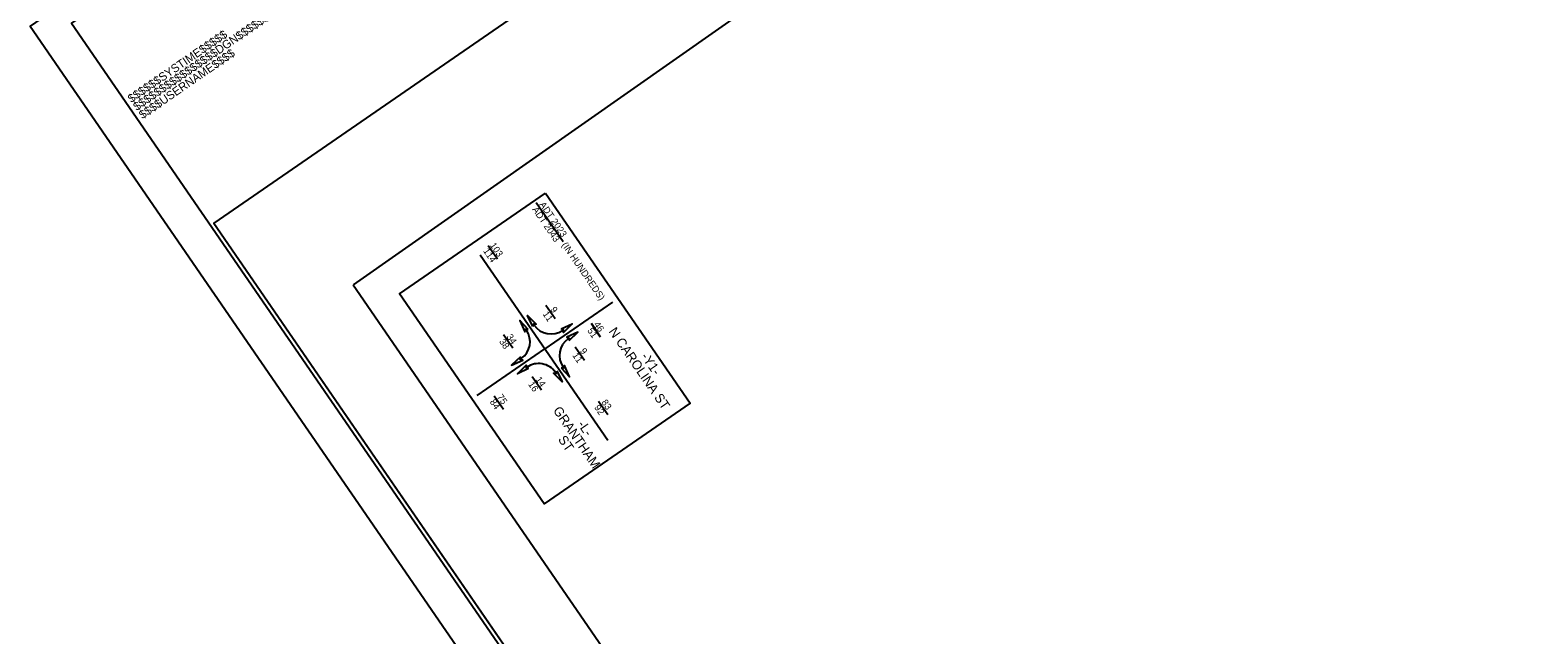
# Model space of a CAD drawing. Extents: x 2297526 to 2298642, y 599613 to 600819.
# Drawn here: x 2297526 to 2298094, y 600216 to 600444 of the extents above; entities that cross this region are included whole.
import ezdxf

# ---------------------------------------------------------------- set-up
doc = ezdxf.new("R2010")
doc.units = 0
for name, color, linetype in [('Default', 7, 'Continuous'), ('Exist DTM Drainline Cogo Comment', 7, 'Continuous'), ('Exist DTM Drainline Cogo Elevation', 7, 'Continuous'), ('Exist Property Iron Pin Cogo Number', 7, 'Continuous'), ('Exist Roads Curbs Cogo Number', 7, 'Continuous'), ('Exist Roads Curbs Cogo Point CELL', 7, 'Continuous'), ('Exist Roads EOP Cogo Elevation', 7, 'Continuous')]:
    doc.layers.add(name, color=color, linetype=linetype)

msp = doc.modelspace()

# ---------------------------------------------------------------- linework, layer by layer
at = {"layer": 'Default'}
for points in [[(2297715.05, 600332.05), (2297713.1, 600336.18), (2297716.33, 600332.93), (2297715.33, 600332.94)], [(2297713.36, 600330.96), (2297710.19, 600334.26), (2297712.07, 600330.08), (2297712.42, 600331.02)], [(2297725.74, 600331.14), (2297729.87, 600333.09), (2297726.63, 600329.86), (2297726.63, 600330.86)], [(2297728.74, 600326.79), (2297732.03, 600329.95), (2297727.86, 600328.07), (2297728.79, 600327.72)], [(2297710.39, 600320.65), (2297707.1, 600317.49), (2297711.28, 600319.37), (2297710.34, 600319.71)], [(2297713.43, 600316.24), (2297709.3, 600314.3), (2297712.54, 600317.53), (2297712.54, 600316.53)], [(2297724.12, 600315.33), (2297726.07, 600311.2), (2297722.84, 600314.45), (2297723.84, 600314.44)], [(2297725.78, 600316.47), (2297728.94, 600313.18), (2297727.06, 600317.36), (2297726.71, 600316.42)]]:
    msp.add_lwpolyline(points, close=True, dxfattribs=at)
for centre, start, end in [((2297706.34, 600326.3), 304.554, 34.554), ((2297721.91, 600336.94), 214.5541, 304.5541), ((2297732.8, 600321.14), 124.554, 214.554), ((2297717.26, 600310.44), 34.5541, 124.5541)]:
    msp.add_arc(centre, 7.69, start, end, dxfattribs=at)
at = {"layer": 'Exist DTM Drainline Cogo Comment'}
msp.add_lwpolyline([(2298629.8, 599981.76), (2298062.67, 600805.27), (2297541.29, 600446.21), (2298108.42, 599622.7)], close=True, dxfattribs=at)
at = {"layer": 'Exist DTM Drainline Cogo Elevation'}
msp.add_lwpolyline([(2298624.28, 599987.07), (2298113.82, 600728.3), (2297594.96, 600370.97), (2298105.42, 599629.74)], close=True, dxfattribs=at)
at = {"layer": 'Exist Property Iron Pin Cogo Number'}
msp.add_lwpolyline([(2297647.43, 600347.7), (2298036.32, 599783), (2298066.14, 599803.53), (2298144.6, 599689.59), (2298480.39, 599975.84), (2298444.85, 600027.45), (2298522.99, 600081.26), (2298287.23, 600423.6), (2298114.33, 600674.66)], close=True, dxfattribs=at)
at = {"layer": 'Exist Roads Curbs Cogo Number'}
msp.add_lwpolyline([(2298113.82, 600728.3), (2297594.98, 600370.97), (2298105.44, 599629.74), (2298525.54, 599919.07), (2298457.47, 600017.93), (2298556.21, 600085.92)], close=True, dxfattribs=at)
at = {"layer": 'Exist Roads Curbs Cogo Point CELL'}
msp.add_lwpolyline([(2298642.42, 599987.17), (2298069.34, 600819.33), (2297525.77, 600444.99), (2298098.85, 599612.83)], close=True, dxfattribs=at)
at = {"layer": 'Exist Roads EOP Cogo Elevation'}
for p, q in [((2297716.36, 600378.69), (2297726.45, 600364.04)), ((2297695.29, 600358.97), (2297743.27, 600289.31)), ((2297698.25, 600362.51), (2297701.72, 600357.47)), ((2297745.05, 600341.23), (2297719.58, 600323.69)), ((2297720.04, 600340.06), (2297723.52, 600335.02)), ((2297737, 600333.27), (2297740.47, 600328.22)), ((2297704.07, 600329.06), (2297707.54, 600324.02)), ((2297694.12, 600306.16), (2297719.58, 600323.69)), ((2297731.04, 600324.39), (2297734.52, 600319.35)), ((2297714.84, 600313.24), (2297718.32, 600308.19)), ((2297700.53, 600306.03), (2297704.01, 600300.98)), ((2297739.84, 600304), (2297743.31, 600298.96))]:
    msp.add_line(p, q, dxfattribs=at)
msp.add_lwpolyline([(2297719.84, 600382.25), (2297774.28, 600303.2), (2297719.29, 600265.33), (2297664.85, 600344.38)], close=True, dxfattribs=at)

# ---------------------------------------------------------------- texts
at = {"layer": 'Exist DTM Drainline Cogo Elevation'}
for s, p in [('$$$$$$$$$$$$$$$$DGN$$$$$$$$$$$$$$$$', (2297565.95, 600413.09)), ('$$$$$$SYSTIME$$$$$', (2297563.89, 600416.08)), ('$$$$USERNAME$$$$', (2297568.1, 600409.98))]:
    msp.add_text(s, height=3.15, rotation=34.5541, dxfattribs=at).set_placement(p)
at = {"layer": 'Exist Roads EOP Cogo Elevation'}
for s, height, p in [('ADT 2043', 2.52, (2297714.72, 600376.06)), ('ADT 2023', 2.52, (2297717.44, 600377.93)), ('114', 2.52, (2297696.25, 600360.47)), ('103', 2.52, (2297698.79, 600362.6)), ('(IN HUNDREDS)', 2.52, (2297725.82, 600362.74)), ('11', 2.52, (2297718.68, 600336.72)), ('9', 2.52, (2297721.53, 600338.42)), ('51', 2.52, (2297735.47, 600330.53)), ('46', 2.52, (2297737.91, 600332.81)), ('N CAROLINA ST', 3.528, (2297743.51, 600330.21)), ('38', 2.52, (2297702.26, 600326.38)), ('34', 2.52, (2297705.02, 600328.2)), ('11', 2.52, (2297729.85, 600321.17)), ('9', 2.52, (2297732.69, 600322.86)), ('-Y1-', 3.528, (2297755.62, 600320.78)), ('16', 2.52, (2297713.21, 600310.3)), ('14', 2.52, (2297715.96, 600312.13)), ('84', 2.52, (2297698.75, 600303.66)), ('75', 2.52, (2297701.46, 600305.55)), ('92', 2.52, (2297738.09, 600301.58)), ('83', 2.52, (2297740.77, 600303.52)), ('GRANTHAM', 3.528, (2297722.54, 600300.48)), (' ST', 3.528, (2297723.69, 600290.65)), ('-L-', 3.528, (2297731.77, 600295.22))]:
    msp.add_text(s, height=height, rotation=304.5541, dxfattribs=at).set_placement(p)

doc.saveas('drawing.dxf')
